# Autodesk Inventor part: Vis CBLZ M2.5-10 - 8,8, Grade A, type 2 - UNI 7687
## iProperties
Created: 2002-05
Part Number: Vis CBLZ M2.5-10 - 8,8, Grade A, type 2 - UNI 7687
Material: Par défaut
Catalog Web Link: www.traceparts.com
Description: Vis CBLZ M2.5-10 - 8,8, Grade A, type 2 - UNI 7687
Document SubType Name: Modélisation
Designer: Flavien MARTY
Control State: 0
Master: False
Checked Out: False
Shininess: 20.0
Length Units: 11269
Angle Units: 11279
Time Units: 11290
Mass Units: 11283
Length Display Precision: 3
Angle Display Precision: 2
Compacted: True
Density: 0.0
Volumn: 0.0
Area: 0.0
PropertySet Name: Model Information
Author: Flavien MARTY
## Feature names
1. Base1
